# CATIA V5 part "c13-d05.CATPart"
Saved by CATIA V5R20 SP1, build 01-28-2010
Part number: Part1
Bounding box of the stored display mesh (mm): x -62.5 to 62.5, y -75 to 75, z 0 to 20
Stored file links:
  D:\v5_r20\psrt_files_downloaded\c13-catia-v5r20-prt\Figure 13-26\c13-d05.CATPart
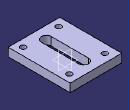
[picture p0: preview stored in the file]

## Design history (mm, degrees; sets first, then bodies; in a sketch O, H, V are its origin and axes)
Body1 (main body)
  Sketch1 on xy-plane, origin (0, 0, 0), H (1, 0, 0), V (0, 1, 0)
    line L1 (62.5, 75) -> (62.5, -75)
    line L2 (62.5, -75) -> (-62.5, -75)
    line L3 (-62.5, -75) -> (-62.5, 75)
    line L4 (-62.5, 75) -> (62.5, 75)
    length L1 = 150
    length L2 = 125
    vertical: L1 V, L3 V
    horizontal: L2 H, L4 H
    equidistance: L1 L3 O, L2 L4 O
  Pad1: profile Sketch1, direction (0, 0, 1), length 20
  Sketch2 on face of Pad1, origin (0, 0, 20), H (1, 0, 0), V (0, 1, 0)
    construction line L1 (0, 45) -> (0, -45)
    point P1 (0, 45)
    line L2 (12, 45) -> (12, -45)
    line L3 (-12, -45) -> (-12, 45)
    arc A1 centre (0, -45) radius 12 from (12, -45) to (-12, -45) cw
    arc A2 centre (0, 45) radius 12 from (-12, 45) to (12, 45) cw
    length L1 = 90
    radius A2 = 12
    coincidence: P1 V
    vertical: L1 V
    tangency: A1 L2, A2 L2, A1 L3, A2 L3
    parallelism: L1 L2
    midpoint: O L1
  Pocket1: profile Sketch2, direction (0, 0, -1), through (limit type 3)
  Sketch3 on face of Pad1, origin (38.7626, -18.4621, 20), H (1, 0, 0), V (0, 1, 0)
    point P1 (5.7374, -38.5379)
    reference projected line E1 (-101.2626, -56.5379) -> (23.7374, -56.5379) from edge [face of Pad1 | face of Pad1]
    reference projected line E2 (23.7374, -56.5379) -> (23.7374, 93.4621) from edge [face of Pad1 | face of Pad1]
    distance P1 E1 = 18
    distance P1 E2 = 18
  Hole1: placed by Sketch3, at (44.5, -57, 20) direction (0, 0, -1), diameter 13, through (limit type 3)
  RectPattern1: of Hole1, direction 1 instances 2, spacing 86, along edge [face of Pad1 | face of Pad1] reversed, direction 2 instances 2, spacing 112, along edge [face of Pad1 | face of Pad1]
